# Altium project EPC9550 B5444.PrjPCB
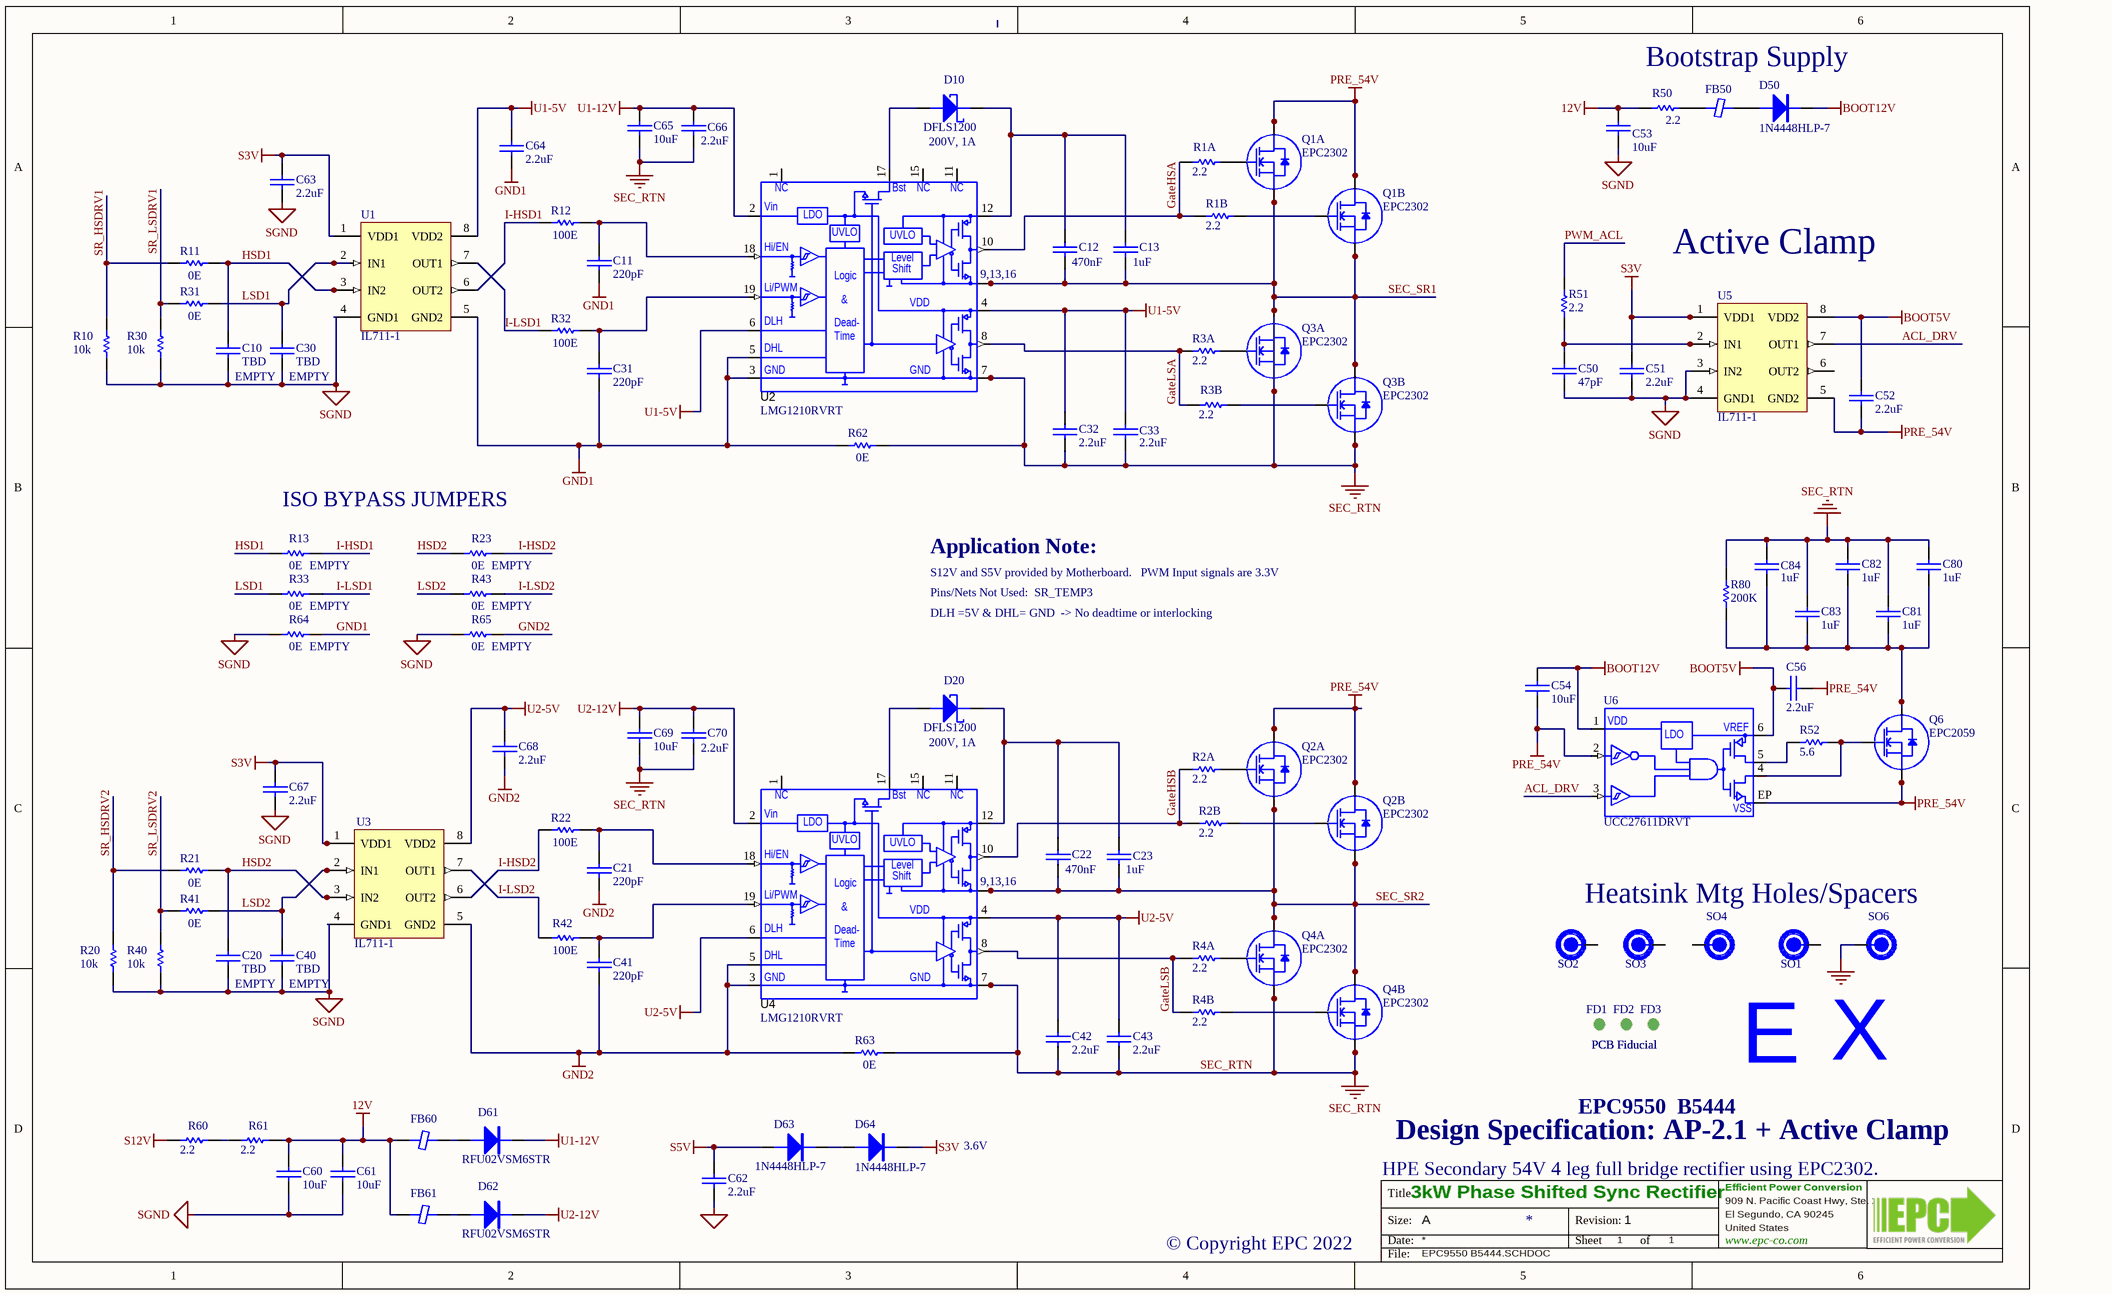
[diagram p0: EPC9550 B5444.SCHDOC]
1 sheet, 107 parts. Net scope: global (net labels, ports and power ports of the same name join across sheets).
Board file: EPC9550 B5444.PCBDOC

## Sheet EPC9550 B5444.SCHDOC: 3kW Phase Shifted Sync Rectifier
size B; Organization: Efficient Power Conversion; Address1: 909 N. Pacific Coast Hwy, Ste. 230; Address2: El Segundo, CA 90245; Address3: United States; Address4: www.epc-co.com; Revision: 1; SheetNumber: 1; SheetTotal: 1

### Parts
C10  EMPTY  value TBD  [CC0402]
C11  value 220pF  [CC0402]  (hidden comment: C1005C0G2A221J050BA)
C12  value 470nF  [CC0402]  (hidden comment: C1005X5R1E474K050BB)
C13  value 1uF  [CC0402]  (hidden comment: C1005X5R1E105K050BC)
C20  EMPTY  value TBD  [CC0402]
C21  value 220pF  [CC0402]  (hidden comment: C1005C0G2A221J050BA)
C22  value 470nF  [CC0402]  (hidden comment: C1005X5R1E474K050BB)
C23  value 1uF  [CC0402]  (hidden comment: C1005X5R1E105K050BC)
C30  EMPTY  value TBD  [CC0402]
C31  value 220pF  [CC0402]  (hidden comment: C1005C0G2A221J050BA)
C32  value 2.2uF  [CC0402]  (hidden comment: GRM155R61E225ME15D)
C33  value 2.2uF  [CC0402]  (hidden comment: GRM155R61E225ME15D)
C40  EMPTY  value TBD  [CC0402]
C41  value 220pF  [CC0402]  (hidden comment: C1005C0G2A221J050BA)
C42  value 2.2uF  [CC0402]  (hidden comment: GRM155R61E225ME15D)
C43  value 2.2uF  [CC0402]  (hidden comment: GRM155R61E225ME15D)
C50  value 47pF  [CC0402]  (hidden comment: CC0402JRNPO9BN470)
C51  value 2.2uF  [CC0402]  (hidden comment: GRM155R61E225ME15D)
C52  value 2.2uF  [CC0402]  (hidden comment: GRM155R61E225ME15D)
C53  value 10uF  [CC0603]  (hidden comment: C1608X5R1E106M080AC)
C54  value 10uF  [CC0603]  (hidden comment: C1608X5R1E106M080AC)
C56  value 2.2uF  [CC0402]  (hidden comment: GRM155R61E225ME15D)
C60  value 10uF  [CC0603]  (hidden comment: C1608X5R1E106M080AC)
C61  value 10uF  [CC0603]  (hidden comment: C1608X5R1E106M080AC)
C62  value 2.2uF  [CC0402]  (hidden comment: GRM155R61E225ME15D)
C63  value 2.2uF  [CC0402]  (hidden comment: GRM155R61E225ME15D)
C64  value 2.2uF  [CC0402]  (hidden comment: GRM155R61E225ME15D)
C65  value 10uF  [CC0603]  (hidden comment: C1608X5R1E106M080AC)
C66  value 2.2uF  [CC0402]  (hidden comment: GRM155R61E225ME15D)
C67  value 2.2uF  [CC0402]  (hidden comment: GRM155R61E225ME15D)
C68  value 2.2uF  [CC0402]  (hidden comment: GRM155R61E225ME15D)
C69  value 10uF  [CC0603]  (hidden comment: C1608X5R1E106M080AC)
C70  value 2.2uF  [CC0402]  (hidden comment: GRM155R61E225ME15D)
C80  value 1uF  [CC0805]  (hidden comment: 08051C105K4Z2A)
C81  value 1uF  [CC0805]  (hidden comment: 08051C105K4Z2A)
C82  value 1uF  [CC0805]  (hidden comment: 08051C105K4Z2A)
C83  value 1uF  [CC0805]  (hidden comment: 08051C105K4Z2A)
C84  value 1uF  [CC0805]  (hidden comment: 08051C105K4Z2A)
D10  MFGPN: DFLS1200  SchDescript: 200V, 1A  [POWERDI-123]  (hidden comment: Diode Schottky)
D20  MFGPN: DFLS1200  SchDescript: 200V, 1A  [POWERDI-123]  (hidden comment: Diode Schottky)
D50  MFGPN: 1N4448HLP-7  [DFN1006-2]  (hidden comment: Diode)
D61  MFGPN: RFU02VSM6STR  [TUMD2SM ROHM]  (hidden comment: Diode)
D62  MFGPN: RFU02VSM6STR  [TUMD2SM ROHM]  (hidden comment: Diode)
D63  MFGPN: 1N4448HLP-7  [DFN1006-2]  (hidden comment: Diode)
D64  MFGPN: 1N4448HLP-7  [DFN1006-2]  (hidden comment: Diode)
FB50  MMZ1005Y182CTD25  [LC0402sml]  (value not drawn)
FB60  MMZ1005Y182CTD25  [LC0402sml]  (value not drawn)
FB61  MMZ1005Y182CTD25  [LC0402sml]  (value not drawn)
FD1  PCB Fiducial  [Fiducial_Board]  (no BOM)
FD2  PCB Fiducial  [Fiducial_Board]  (no BOM)
FD3  PCB Fiducial  [Fiducial_Board]  (no BOM)
LB2  Hot_SIGN  [Hot_SIGN]  (value not drawn)  (no BOM)
Q1A  EPC2302  [D0606_100V]
Q1B  EPC2302  [D0606_100V]
Q2A  EPC2302  [D0606_100V]
Q2B  EPC2302  [D0606_100V]
Q3A  EPC2302  [D0606_100V]
Q3B  EPC2302  [D0606_100V]
Q4A  EPC2302  [D0606_100V]
Q4B  EPC2302  [D0606_100V]
Q6  EPC2059  [D0298T34M]
R1A  value 2.2  [RC0402]  (hidden comment: RMCF0402FT2R0)
R1B  value 2.2  [RC0402]  (hidden comment: RMCF0402FT2R0)
R2A  value 2.2  [RC0402]  (hidden comment: RMCF0402FT2R0)
R2B  value 2.2  [RC0402]  (hidden comment: RMCF0402FT2R0)
R3A  value 2.2  [RC0402]  (hidden comment: RMCF0402FT2R0)
R3B  value 2.2  [RC0402]  (hidden comment: RMCF0402FT2R0)
R4A  value 2.2  [RC0402]  (hidden comment: RMCF0402FT2R0)
R4B  value 2.2  [RC0402]  (hidden comment: RMCF0402FT2R0)
R10  value 10k  [RC0402]  (hidden comment: ERJ-2RKF1002X)
R11  value 0E  [RC0402]  (hidden comment: ERJ-2GE0R00X)
R12  value 100E  [RC0402]  (hidden comment: RC0402FR-07100RL)
R13  EMPTY  value 0E  [RC0402]
R20  value 10k  [RC0402]  (hidden comment: ERJ-2RKF1002X)
R21  value 0E  [RC0402]  (hidden comment: ERJ-2GE0R00X)
R22  value 100E  [RC0402]  (hidden comment: RC0402FR-07100RL)
R23  EMPTY  value 0E  [RC0402]
R30  value 10k  [RC0402]  (hidden comment: ERJ-2RKF1002X)
R31  value 0E  [RC0402]  (hidden comment: ERJ-2GE0R00X)
R32  value 100E  [RC0402]  (hidden comment: RC0402FR-07100RL)
R33  EMPTY  value 0E  [RC0402]
R40  value 10k  [RC0402]  (hidden comment: ERJ-2RKF1002X)
R41  value 0E  [RC0402]  (hidden comment: ERJ-2GE0R00X)
R42  value 100E  [RC0402]  (hidden comment: RC0402FR-07100RL)
R43  EMPTY  value 0E  [RC0402]
R50  value 2.2  [RC0402]  (hidden comment: RMCF0402FT2R0)
R51  value 2.2  [RC0402]  (hidden comment: RMCF0402FT2R0)
R52  value 5.6  [RC0402]  (hidden comment: ERJ-U02J5R6X)
R60  value 2.2  [RC0402]  (hidden comment: RMCF0402FT2R0)
R61  value 2.2  [RC0402]  (hidden comment: RMCF0402FT2R0)
R62  value 0E  [RC0402]  (hidden comment: ERJ-2GE0R00X)
R63  value 0E  [RC0402]  (hidden comment: ERJ-2GE0R00X)
R64  EMPTY  value 0E  [RC0402]
R65  EMPTY  value 0E  [RC0402]
R80  value 200K  [RC1206]  (hidden comment: TBD)
S2  AntiStat_Sign  [AS_SIGN]  (value not drawn)  (no BOM)
SO1  EPC_Thermal_Spacer_SMD_M2  [9774010243R]  (value not drawn)
SO2  EPC_Thermal_Spacer_SMD_M2  [9774010243R]  (value not drawn)
SO3  EPC_Thermal_Spacer_SMD_M2  [9774010243R]  (value not drawn)
SO4  EPC_Thermal_Spacer_SMD_M2  [9774010243R]  (value not drawn)
SO6  EPC_Thermal_Spacer_SMD_M2  [9774010243R]  (value not drawn)
U1  IL711-1  [MSOP8]
U2  MFGPN: LMG1210RVRT  [WQFN-19]  (hidden comment: LMG1210RVR)
U3  IL711-1  [MSOP8]
U4  MFGPN: LMG1210RVRT  [WQFN-19]  (hidden comment: LMG1210RVR)
U5  IL711-1  [MSOP8]
U6  MFGPN: UCC27611DRVT  [6-WDFN]  (hidden comment: UCC27611DRV)

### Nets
12V: C53.2 C60.2 C61.1 FB60.1 FB61.1 R50.1 R61.2
BOOT5V: C52.1 C56.2 U5.8(VDD2) U6.6(VREF)
BOOT12V: C54.2 D50.K U6.1(VDD)
GND1: C11.2 C31.2 C64.2 R62.1 R64.2 U1.5(GND2) U2.3(GND) U2.5(DHL)
GND2: C21.2 C41.2 C68.2 R63.1 R65.2 U3.5(GND2) U4.3(GND) U4.5(DHL)
PRE_54V: C52.2 C54.1 C56.1 Q1A.3(D) Q1A.5(D) Q1A.7(D) Q1B.3(D) Q1B.5(D) Q1B.7(D) Q2A.3(D) Q2A.5(D) Q2A.7(D) Q2B.3(D) Q2B.5(D) Q2B.7(D) Q6.2(S) Q6.4(S) Q6.6(S) U5.5(GND2) U6.2(INB) U6.EP(VSS)
S3V: C51.1 C63.1 C67.1 D64.K U1.1(VDD1) U3.1(VDD1) U5.1(VDD1)
S5V: C62.1 D63.A
S12V: R60.1
SEC_RTN: C32.2 C33.2 C42.2 C43.2 C65.1 C66.2 C69.1 C70.2 C80.2 C81.2 C82.2 C83.2 C84.2 Q3A.2(S) Q3A.4(S) Q3A.6(S) Q3B.2(S) Q3B.4(S) Q3B.6(S) Q4A.2(S) Q4A.4(S) Q4A.6(S) Q4B.2(S) Q4B.4(S) Q4B.6(S) R62.2 R63.2 R80.2 SO6.1 U2.7(GND) U2.20(LS_DAP) U4.7(GND) U4.20(LS_DAP)
SGND: C10.2 C20.2 C30.2 C40.2 C50.2 C51.2 C53.1 C60.1 C61.2 C62.2 C63.2 C67.2 R10.2 R20.2 R30.2 R40.2 R64.1 R65.1 U1.4(GND1) U3.4(GND1) U5.3(IN2) U5.4(GND1)
U1-5V: C32.1 C33.1 C64.1 U1.8(VDD2) U2.4(VDD) U2.6(DLH)
U1-12V: C65.2 C66.1 D61.K U2.2(VIN)
U2-5V: C42.1 C43.1 C68.1 U3.8(VDD2) U4.4(VDD) U4.6(DLH)
U2-12V: C69.2 C70.1 D62.K U4.2(VIN)
ACL_DRV: U5.7(OUT1) U6.3(IN)
GateHSA: R1A.1 R1B.1 U2.10(HO)
GateHSB: R2A.1 R2B.1 U4.10(HO)
GateLSA: R3A.1 R3B.1 U2.8(LO)
GateLSB: R4A.1 R4B.1 U4.8(LO)
HSD1: C10.1 R11.2 R13.1 U1.3(IN2)
HSD2: C20.1 R21.2 R23.1 U3.3(IN2)
I-HSD1: R12.1 R13.2 U1.6(OUT2)
I-HSD2: R22.1 R23.2 U3.6(OUT2)
I-LSD1: R32.1 R33.2 U1.7(OUT1)
I-LSD2: R42.1 R43.2 U3.7(OUT1)
LSD1: C30.1 R31.2 R33.1 U1.2(IN1)
LSD2: C40.1 R41.2 R43.1 U3.2(IN1)
PWM_ACL: R51.1
SEC_SR1: C12.2 C13.2 Q1A.2(S) Q1A.4(S) Q1A.6(S) Q1B.2(S) Q1B.4(S) Q1B.6(S) Q3A.3(D) Q3A.5(D) Q3A.7(D) Q3B.3(D) Q3B.5(D) Q3B.7(D) U2.9(HS) U2.13(HS) U2.14(NC1) U2.16(HS) U2.21(HS_DAP)
SEC_SR2: C22.2 C23.2 Q2A.2(S) Q2A.4(S) Q2A.6(S) Q2B.2(S) Q2B.4(S) Q2B.6(S) Q4A.3(D) Q4A.5(D) Q4A.7(D) Q4B.3(D) Q4B.5(D) Q4B.7(D) U4.9(HS) U4.13(HS) U4.14(NC1) U4.16(HS) U4.21(HS_DAP)
SR_HSDRV1: R10.1 R11.1
SR_HSDRV2: R20.1 R21.1
SR_LSDRV1: R30.1 R31.1
SR_LSDRV2: R40.1 R41.1
NetC11_1: C11.1 R12.2 U2.18(HI/EN)
NetC12_1: C12.1 C13.1 D10.K U2.12(HB)
NetC21_1: C21.1 R22.2 U4.18(HI/EN)
NetC22_1: C22.1 C23.1 D20.K U4.12(HB)
NetC31_1: C31.1 R32.2 U2.19(LI/PWM)
NetC41_1: C41.1 R42.2 U4.19(LI/PWM)
NetC50_1: C50.1 R51.2 U5.2(IN1)
NetC80_1: C80.1 C81.1 C82.1 C83.1 C84.1 Q6.3(D) Q6.5(D) R80.1
NetD10_A: D10.A U2.17(BST)
NetD20_A: D20.A U4.17(BST)
NetD50_A: D50.A FB50.2
NetD61_A: D61.A FB60.2
NetD62_A: D62.A FB61.2
NetD63_K: D63.K D64.A
NetFB50_1: FB50.1 R50.2
NetQ1A_1: Q1A.1(G) R1A.2
NetQ1B_1: Q1B.1(G) R1B.2
NetQ2A_1: Q2A.1(G) R2A.2
NetQ2B_1: Q2B.1(G) R2B.2
NetQ3A_1: Q3A.1(G) R3A.2
NetQ3B_1: Q3B.1(G) R3B.2
NetQ4A_1: Q4A.1(G) R4A.2
NetQ4B_1: Q4B.1(G) R4B.2
NetQ6_1: Q6.1(G) R52.1 U6.4(Nout)
NetR52_2: R52.2 U6.5(Pout)
NetR60_2: R60.2 R61.1

Not connected (* = marked no-connect by the designer): SO1 1; SO2 1; SO3 1; SO4 1; U2 1(NC) 11(NC) 15(NC); U4 1(NC) 11(NC) 15(NC); U5 6(OUT2)

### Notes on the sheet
- Bootstrap Supply
- Active Clamp
- ISO BYPASS JUMPERS
- Application Note:
- Pins/Nets Not Used:  SR_TEMP3
- S12V and S5V provided by Motherboard.   PWM Input signals are 3.3V
- DLH =5V & DHL= GND  -> No deadtime or interlocking
- Heatsink Mtg Holes/Spacers
- 3.6V
- HPE Secondary 54V 4 leg full bridge rectifier using EPC2302.
- Design Specification: AP-2.1 + Active Clamp
- EPC9550  B5444
- © Copyright EPC 2022

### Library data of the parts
C10 C20 C30 C40 = C0402-TBD
C11 C21 C31 C41 = C0402-220pF-100V-C0G-5%: EPC Part Number: C-0402-040; MFG: TDK; SchDescript: 220pF 100V; QSGdescript: CAP CER 220PF 100V C0G 0402; Voltage: 100; Tolerance: 0.05; Tempco: C0G/NP0; Material: Ceramic
C12 C22 = C0402-470nF-25V-X5R-10%: EPC Part Number: C-0402-054; MFG: TDK; SchDescript: 470nF 25V; QSGdescript: CAP CER 0.47UF 25V X5R 0402; Voltage: 25; Tolerance: 0.1; Tempco: X5R; Material: Ceramic
C13 C23 = C0402-1uF-25V-X5R-10%: EPC Part Number: C-0402-025; MFG: TDK; SchDescript: 1uF 25V; QSGdescript: CAP CER 1UF 25V X5R 0402; Voltage: 25; Tolerance: 0.1; Tempco: X5R; Material: Ceramic
C32 C33 C42 C43 C62-C64 C66-C68 C70 = C0402-2.2uF-25V-X5R-20%-Murata: MFG: Murata; SchDescript: 2.2uF 25V; QSGdescript: CAP CER 2.2UF 25V X5R 0402; Voltage: 25; Tolerance: 0.2; Tempco: X5R; Material: Ceramic
C50 = C0402-47pF-50V-C0G/NP0-5%: EPC Part Number: C-0402-012; MFG: Yageo; SchDescript: 47pF 50V; QSGdescript: CAP CER 47PF 50V C0G/NPO 0402; Voltage: 50; Tolerance: 0.05; Material: Ceramic
C51 C52 C56 = C0402-2.2uF-25V-X5R-20%-Murata: Tempco: X5R; SchDescript: 2.2uF 25V; QSGdescript: CAP CER 2.2UF 25V X5R 0402; Voltage: 25; Tolerance: 0.2; Material: Ceramic; MFG: Murata
C53 C54 C60 C61 C65 C69 = C0603-10uF-25V-X5R-20%: MFG: TDK; SchDescript: 10uF 25V; QSGdescript: CAP CER 10UF 25V X5R 0603; Voltage: 25; Tolerance: 0.2; Tempco: X5R; Material: Ceramic
C80-C84 = C0805-1uF-100V-X7R-10%: EPC Part Number: C-0805-048; Tempco: X7R; SchDescript: 1uF 100V; QSGdescript: CAP CER 1UF 100V X7R 0805; Voltage: 100; Tolerance: 0.1; Material: Ceramic; MFG: AVX
D10 D20 = DS-200V-1A-DFLS1200: EPC Part Number: D-009; QSGdescript: DIODE SCHOTTKY 200V POWERDI123; Voltage Rating: 200V; Current Rating: 1A; MFG: Diodes Inc.
D50 D63 D64 = D-80V-125mA-1N4448HLP-7: SchDescript: 80V, 125mA; QSGdescript: DIODE GEN PURP 80V 125MA 2DFN; Voltage Rating: 80V; Current Rating: 125mA; MFG: Diodes Inc.; F22: 1N4448HLPDIDKR-ND
D61 D62 = D-600V-200mA-RFU02VSM6STR: EPC Part Number: D-042; MFG: Rohm; SchDescript: 600V 200mA; QSGdescript: DIODE GP 600V 200mA TUMD2SM; Voltage Rating: 600V; Current Rating: 200mA
FB50 FB60 FB61 = FB0402_1.8kE_150mA_0402: SchDescript: 1.8kE @ 100MHz 150mA; QSGdescript: FERRITE BEAD 1.8 KOHM 0402 1LN; MFG: TDK; Value: 1.8kE @ 100MHz; DCR: 850mE; Current Rating: 150mA; Tolerance: 0.25
FD1-FD3 = Fiducial_Board: Value: Fiducial 40mil; SchDescript: Fiducial_Board Round Open Round .040
LB2 = Hot_Sign: Hot Symbol
Q1A Q1B Q2A Q2B Q3A Q3B Q4A Q4B = EPC2302: 100V 100A 1.9mE; MFG: EPC; SchDescript: 100V, 1.9mE
Q6 = EPC2059: 170V 25A 9mE; SchDescript: 170V 6.8mE 24A; MFG: EPC
R1A R1B R2A R2B R3A R3B R4A R4B R50 R60 R61 = R0402-2.2-1%-1/16W-Thickfilm: EPC Part Number: R-0402-016; Tolerance: 0.01; MFG: Stackpole; SchDescript: 2.2 1/16W; QSGdescript: RES 2.05 OHM 1% 1/16W 0402; Power Rating: 1/16
R10 R20 R30 R40 = R0402-10k-1%-0.1W-Thickfilm: EPC Part Number: R-0402-011; SchDescript: 10k 0.1W; QSGdescript: RES SMD 10K OHM 1% 1/10W 0402; Power Rating: 0.1; Tolerance: 0.01; MFG: Panasonic
R11 R21 R31 R41 R62 R63 = R0402-0-0.1W: EPC Part Number: R-0402-004; SchDescript: 0E 0.1W; QSGdescript: RES SMD 0 OHM JUMPER 1/10W 0402; Power Rating: 0.1; MFG: Panasonic
R12 R22 R32 R42 = R0402-100-1%-0.1W-Thickfilm: SchDescript: 100E 1/16W 1%; QSGdescript: RES SMD 100 OHM 1% 1/10W 0402; Power Rating: 1/16; Tolerance: 0.01; MFG: Yageo
R13 R23 R33 R43 R64 R65 = R0402-0-0.1W: EPC Part Number: R-0402-004; SchDescript: 0E 0.1W; QSGdescript: RES SMD 0 OHM JUMPER 1/10W 0402; Power Rating: 0.1; MFG: Panasonic; MFGPN: ERJ-2GE0R00X
R51 = R0402-2.2-1%-1/16W-Thickfilm: EPC Part Number: R-0402-016; SchDescript: 2.2 1/16W; QSGdescript: RES 2.05 OHM 1% 1/16W 0402; Power Rating: 1/16; Tolerance: 0.01; MFG: Stackpole
R52 = R0402-5.6-5%-0.1W-ThickFilm: SchDescript: 5.6 0.1W; QSGdescript: RES 5.6 OHM 5% 1/10W 0402 SMD; Power Rating: 0.1; Tolerance: 0.05; MFG: Panasonic
R80 = R1206-TBD
S2 = AntiStat_Sign: Anti-static caution sign; Descript: Anti-Static Symbol
SO1-SO4 SO6 = EPC_SMD_Thermal_SpacerM2x1mm: Descript: Round Standoff Threaded M2x0.4 Steel 0.039" (1.00mm); MFG: Wurth; Value: Round Standoff M2x0.4  1.00mm
U1 U3 U5 = IL711-1: Digittal Isolator,150Mbps, 6KV, 10nS Delay MSOP
U2 U4 = LMG1210RVRT: EPC Part Number: IC-109; SchDescript: 300V Half Bridge Gate Driver; Voltage Rating: 300; MFG: Texas Instruments
U6 = UCC27611DRVT: EPC Part Number: IC-004; SchDescript: Single 5V Gate Driver; MFG: Texas Instruments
